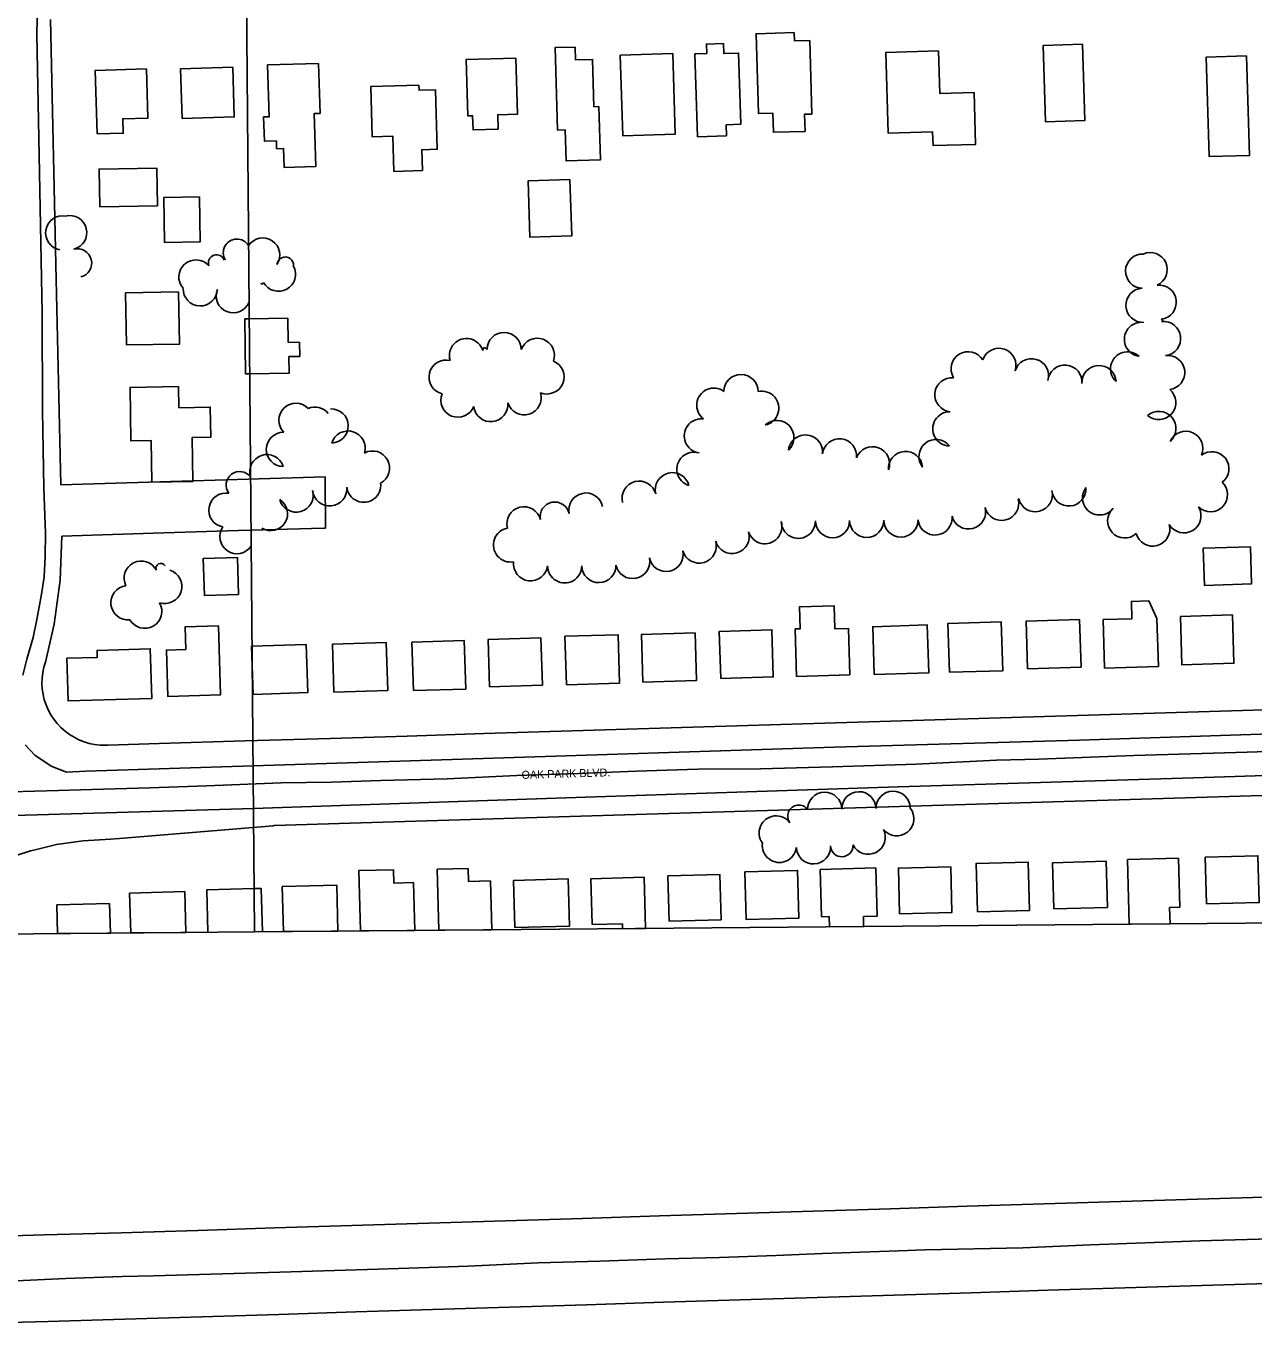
# Model space of a CAD drawing. Extents: x -2233 to 187241, y 4582 to 150524.
# Drawn here: x 114881 to 115599, y 57158 to 57919 of the extents above; entities that cross this region are included whole.
import ezdxf

# ---------------------------------------------------------------- set-up
doc = ezdxf.new("R2010")
doc.units = 0
for name, color, linetype in [('60', 7, 'Continuous'), ('BLDG', 7, 'Continuous'), ('GE_X_CL_2000', 7, 'Continuous'), ('GRID', 7, 'Continuous'), ('ROAD', 7, 'Continuous'), ('ROAD-NAME', 7, 'Continuous'), ('RW_X_Fee_RW', 7, 'Continuous'), ('TREES', 7, 'Continuous')]:
    doc.layers.add(name, color=color, linetype=linetype)

msp = doc.modelspace()

# ---------------------------------------------------------------- linework, layer by layer
at = {"layer": '60'}
for p, q in [((115014.43, 57389.55), (114990.89, 60087.23)), ((114990.89, 60087.23), (115014.43, 57389.55)), ((120014.24, 57433.19), (115014.43, 57389.55)), ((115014.43, 57389.55), (110014.63, 57345.92))]:
    msp.add_line(p, q, dxfattribs=at)
at = {"layer": 'BLDG'}
for p, q in [((115011.31, 57748.02), (115033.94, 57748.41)), ((115524.99, 57431.91), (115554.72, 57432.72)), ((115526.01, 57394.02), (115524.99, 57431.91)), ((115554.72, 57432.72), (115555.5, 57403.96)), ((115075.48, 57425.39), (115095.67, 57425.93)), ((115076.44, 57390.1), (115075.48, 57425.39)), ((115095.67, 57425.93), (115095.89, 57418.06)), ((115121.31, 57426.13), (115139.31, 57426.62)), ((115122.26, 57390.5), (115121.31, 57426.13)), ((115139.31, 57426.62), (115139.51, 57418.99)), ((115377.77, 57426.92), (115345.3, 57426.05)), ((115345.3, 57426.05), (115346.05, 57398.37)), ((115378.54, 57398.69), (115377.77, 57426.92)), ((115062.52, 57416.9), (115030.67, 57416.04)), ((115030.67, 57416.04), (115031.38, 57389.7)), ((115063.25, 57389.98), (115062.52, 57416.9)), ((115095.89, 57418.06), (115107.42, 57418.37)), ((115107.42, 57418.37), (115108.17, 57390.37)), ((115139.51, 57418.99), (115152.51, 57419.34)), ((115152.51, 57419.34), (115153.28, 57390.77)), ((115242.28, 57421.51), (115211.19, 57420.67)), ((115211.19, 57420.67), (115211.92, 57393.8)), ((115243.1, 57391.55), (115242.28, 57421.51)), ((114973.6, 57413.16), (114941.4, 57412.29)), ((114941.4, 57412.29), (114942.03, 57388.92)), ((114974.24, 57389.2), (114973.6, 57413.16)), ((114929.69, 57406.18), (114898.82, 57405.35)), ((114898.82, 57405.35), (114899.28, 57388.55)), ((114930.16, 57388.82), (114929.69, 57406.18)), ((115555.5, 57403.96), (115549.55, 57403.8)), ((115549.55, 57403.8), (115549.81, 57394.23)), ((115211.92, 57393.8), (115229.59, 57394.29)), ((115229.59, 57394.29), (115229.67, 57391.43)), ((115346.05, 57398.37), (115350.46, 57398.49)), ((115350.46, 57398.49), (115350.62, 57392.49)), ((115350.62, 57392.49), (115370.64, 57392.66)), ((115370.48, 57398.47), (115378.54, 57398.69)), ((115370.64, 57392.66), (115370.48, 57398.47)), ((115549.81, 57394.23), (115526.01, 57394.02)), ((114899.28, 57388.55), (114930.16, 57388.82)), ((114942.03, 57388.92), (114974.24, 57389.2)), ((115031.38, 57389.7), (115063.25, 57389.98)), ((115108.17, 57390.37), (115076.44, 57390.1)), ((115153.28, 57390.77), (115122.26, 57390.5)), ((115229.67, 57391.43), (115243.1, 57391.55))]:
    msp.add_line(p, q, dxfattribs=at)
for points in [[(115330.08, 57915.35), (115330.22, 57910.44), (115339.11, 57910.7), (115340.42, 57867.69), (115336.07, 57867.55), (115336.37, 57857.58), (115317.89, 57857.02), (115317.54, 57868.27), (115309.12, 57868.02), (115307.7, 57914.68)], [(115201.94, 57906.89), (115202.17, 57899.37), (115212.06, 57899.67), (115212.9, 57871.95), (115215.72, 57872.03), (115216.67, 57840.91), (115196.66, 57840.31), (115196.11, 57858.41), (115191.71, 57858.27), (115190.23, 57906.52)], [(115258.97, 57903.04), (115260.41, 57855.94), (115229.78, 57855.01), (115228.34, 57902.11)], [(115290.5, 57854.94), (115290.3, 57861.48), (115298.8, 57861.73), (115297.53, 57903.35), (115288.8, 57903.08), (115288.63, 57908.86), (115278.72, 57908.57), (115278.88, 57903.15), (115272.01, 57902.94), (115273.49, 57854.42)], [(115414.45, 57904.66), (115415.21, 57879.64), (115435.21, 57880.24), (115436.13, 57849.99), (115411.23, 57849.23), (115410.98, 57857.25), (115385.06, 57856.45), (115383.62, 57903.72)], [(115498.54, 57908.48), (115499.9, 57863.87), (115476.94, 57863.17), (115475.58, 57907.78)], [(114972.04, 57865.06), (115002.62, 57866), (115001.73, 57895.07), (114971.15, 57894.13)], [(115051.92, 57897.3), (115052.81, 57868.11), (115049.32, 57868), (115050.27, 57836.98), (115031.82, 57836.41), (115031.47, 57847.52), (115027.36, 57847.4), (115027.22, 57851.99), (115020.18, 57851.78), (115019.75, 57866), (115023.02, 57866.1), (115022.09, 57896.39)], [(115167.24, 57900.43), (115168.25, 57867.69), (115156.66, 57867.34), (115156.91, 57858.91), (115142.24, 57858.46), (115141.99, 57866.74), (115139.2, 57866.66), (115138.19, 57899.55)], [(115594.52, 57901.73), (115596.3, 57843.52), (115572.79, 57842.8), (115571.02, 57901.01)], [(114922.42, 57856.04), (114937.65, 57856.51), (114937.39, 57864.93), (114952.11, 57865.37), (114951.24, 57894.12), (114921.3, 57893.22)], [(115110.58, 57884.6), (115110.66, 57881.59), (115120.25, 57881.88), (115121.32, 57847.13), (115112.27, 57846.85), (115112.64, 57834.63), (115095.96, 57834.13), (115095.33, 57854.74), (115083.32, 57854.37), (115082.41, 57883.74)], [(114923.93, 57813.53), (114957.7, 57814.13), (114957.31, 57836.11), (114923.54, 57835.5)], [(115198.92, 57829.37), (115199.93, 57796.42), (115175.47, 57795.67), (115174.46, 57828.62)], [(114982.24, 57819.24), (114982.71, 57793.03), (114961.8, 57792.66), (114961.34, 57818.86)], [(114970.04, 57763.71), (114970.58, 57733.24), (114939.59, 57732.69), (114939.04, 57763.16)], [(114970.02, 57708.36), (114970.24, 57696.01), (114988.51, 57696.34), (114988.81, 57678.78), (114977.97, 57678.58), (114978.43, 57652.89), (114954.45, 57652.46), (114954.02, 57676.82), (114942.19, 57676.62), (114941.63, 57707.86)], [(115569.9, 57592.15), (115597.44, 57593), (115596.78, 57614.69), (115569.24, 57613.85)], [(115004.47, 57608.5), (115005.13, 57586.89), (114985.11, 57586.27), (114984.45, 57607.89)], [(115510.67, 57572.14), (115527.54, 57572.65), (115527.23, 57582.79), (115537.5, 57583.1), (115542.18, 57572.75), (115543.04, 57544.67), (115511.54, 57543.71)], [(115330.56, 57566.74), (115333.62, 57566.83), (115333.23, 57579.63), (115353.34, 57580.24), (115353.75, 57566.75), (115361.7, 57566.99), (115362.53, 57539.89), (115331.41, 57538.95)], [(115555.9, 57573.91), (115586.27, 57574.84), (115587.14, 57546.57), (115556.76, 57545.65)], [(114974.26, 57554.69), (114973.87, 57567.83), (114993.28, 57568.42), (114994.52, 57528.07), (114963.76, 57527.13), (114962.93, 57554.35)], [(115376.88, 57540.04), (115408.74, 57541.01), (115407.88, 57568.98), (115376.02, 57568)], [(115420.82, 57541.31), (115451.97, 57542.26), (115451.1, 57570.82), (115419.95, 57569.87)], [(115466.5, 57543.4), (115497.79, 57544.35), (115496.94, 57572.14), (115465.66, 57571.18)], [(115107.35, 57530.6), (115137.95, 57531.53), (115137.08, 57559.82), (115106.48, 57558.88)], [(115151.94, 57532.85), (115182.78, 57533.78), (115181.94, 57561.44), (115151.1, 57560.5)], [(115196.85, 57534.09), (115227.9, 57535.04), (115227.04, 57563.31), (115195.98, 57562.36)], [(115241.57, 57535.54), (115272.9, 57536.5), (115272.05, 57564.34), (115240.72, 57563.39)], [(115287.05, 57537.68), (115317.81, 57538.62), (115316.97, 57566.19), (115286.21, 57565.25)], [(114904.62, 57549.53), (114922.47, 57550.07), (114922.35, 57554.1), (114953.51, 57555.05), (114954.39, 57526.09), (114905.38, 57524.6)], [(115013.59, 57528.44), (115045.56, 57529.42), (115044.69, 57557.5), (115012.74, 57556.53)], [(115060.84, 57529.65), (115092.34, 57530.61), (115091.48, 57558.65), (115059.99, 57557.69)], [(115437.18, 57401.29), (115467.57, 57402.1), (115466.81, 57430.37), (115436.42, 57429.55)], [(115481.86, 57402.99), (115513.22, 57403.83), (115512.49, 57430.82), (115481.13, 57429.97)], [(115571.11, 57405.87), (115601.95, 57406.7), (115601.22, 57434.05), (115570.38, 57433.22)], [(115256.91, 57395.83), (115287.26, 57396.64), (115286.55, 57423.07), (115256.2, 57422.25)], [(115301.17, 57424.66), (115332.04, 57425.49), (115332.8, 57397.64), (115301.92, 57396.81)], [(115391.67, 57400.14), (115422.3, 57400.96), (115421.59, 57427.63), (115390.94, 57426.82)], [(115166.64, 57392.13), (115198.64, 57392.99), (115197.9, 57420.52), (115165.9, 57419.66)]]:
    msp.add_lwpolyline(points, close=True, dxfattribs=at)
for points in [[(115011.59, 57715.81), (115009.25, 57715.77), (115008.68, 57747.96), (115011.31, 57748.02)], [(115033.94, 57748.41), (115034.2, 57734.15), (115040.72, 57734.26), (115040.86, 57726), (115034.59, 57725.89), (115034.77, 57716.22), (115011.59, 57715.81)], [(115012.98, 57556.53), (115012.74, 57556.53), (115013.07, 57545.53)], [(115014.21, 57414.85), (114986.46, 57414.11), (114987.13, 57389.32)], [(115019.01, 57389.59), (115018.32, 57414.96), (115014.21, 57414.85)]]:
    msp.add_lwpolyline(points, dxfattribs=at)
at = {"layer": 'GE_X_CL_2000'}
for points in [[(114844.17, 57470.72), (114899.9, 57472.29), (114912.73, 57472.55), (114953.21, 57473.76), (114986.42, 57475.03), (115030.1, 57476.62), (115059.54, 57477.06), (115088.32, 57477.98), (115127.09, 57479.11), (115167.82, 57480.89), (115203.99, 57482.2), (115237.88, 57483.56), (115273.59, 57484.65), (115310.42, 57484.92), (115352.49, 57486.1), (115401.28, 57487.56), (115448.38, 57489.87), (115473.17, 57490.54), (115528.63, 57492.67), (115594.96, 57494.66), (115658.5, 57496.72)], [(114858.27, 57184.68), (114904.11, 57186.92), (114937.03, 57188.09), (114955.27, 57188.5), (115029.17, 57190.61), (115086.75, 57192.41), (115110.59, 57193.19), (115139.46, 57194.2), (115180.24, 57196.08), (115216.42, 57197.02), (115254.52, 57198.35), (115286.35, 57199.19), (115319.37, 57200.28), (115346.62, 57201.54), (115391.12, 57203.12), (115406.61, 57203.69), (115463.73, 57204.93), (115503.24, 57206.59), (115567.34, 57208.97), (115643.21, 57210.98)]]:
    msp.add_lwpolyline(points, dxfattribs=at)
at = {"layer": 'GRID'}
msp.add_line((114990.89, 60087.23), (115014.43, 57389.55), dxfattribs=at)
msp.add_line((114990.89, 60087.23), (115014.43, 57389.55), dxfattribs=at)
at = {"layer": 'ROAD'}
msp.add_line((115013.81, 57461.73), (115030.67, 57462.22), dxfattribs=at)
for points in [[(114878.95, 57539.73), (114881.34, 57548.93), (114884.93, 57561.7), (114887.32, 57573.15), (114889.85, 57587.03), (114891.36, 57597.23), (114891.94, 57609.06), (114892.28, 57622.76), (114891.32, 57649.06), (114890.5, 57694.3), (114890.2, 57751.26), (114888.23, 57853.77), (114887.18, 57913.98), (114887.33, 57923.61), (114890.34, 57929.18), (114896.04, 57933.49), (114902.55, 57935.42), (114916.63, 57935.47), (115009.65, 57938.08)], [(115967.66, 57397.87), (115967.22, 57439.54), (115967.02, 57653.57), (115942.42, 57654.18), (115942.42, 57570.13), (115943.09, 57551.47), (115943.01, 57542.96), (115940.75, 57535.02), (115936.99, 57528.64), (115931.48, 57524.14), (115925.27, 57520.39), (115917.82, 57517.03), (115907.8, 57515.66), (115875.7, 57514.71), (115738.38, 57509.58), (115496.79, 57501.73), (115353.35, 57497.56), (115136.04, 57490.56), (115013.59, 57486.62)], [(115013.59, 57486.62), (114915.79, 57483.48), (114904.41, 57482.99), (114895.58, 57486.46), (114886.02, 57492.85), (114880.4, 57498.92)], [(115030.67, 57462.22), (115208.05, 57468.23), (115390.86, 57474.29), (115563.6, 57479.61), (115858.58, 57489.26), (115890.12, 57490.47), (115911.08, 57491.13), (115918.59, 57490.92), (115925.1, 57488.73), (115930.47, 57485.34), (115935.23, 57480.33), (115938.73, 57475.82), (115942.03, 57469.74), (115943.09, 57465.3), (115943.56, 57448.77), (115943.85, 57397.67)], [(114786.02, 57387.56), (114797.2, 57403.6), (114820.03, 57436.87), (114826.3, 57443.87), (114833.51, 57449.49), (114840.9, 57453.18), (114850.8, 57456.35), (114858.87, 57457.28), (114887.4, 57457.98), (115013.81, 57461.73)]]:
    msp.add_lwpolyline(points, dxfattribs=at)
at = {"layer": 'RW_X_Fee_RW'}
for p, q in [((114901.15, 57650.97), (115055.81, 57655.69)), ((115055.81, 57655.69), (115055.94, 57625.68)), ((114927.3, 57498.7), (114928.83, 57498.74))]:
    msp.add_line(p, q, dxfattribs=at)
for points in [[(114895.1, 57922.96), (114898.49, 57770.94), (114899.82, 57710.95), (114901.15, 57650.97)], [(114892.19, 57547.32), (114897.36, 57569.5), (114900.88, 57595.13), (114901.82, 57620.98)], [(114901.82, 57620.98), (114955.1, 57622.6), (115005.08, 57624.13), (115055.06, 57625.65), (115055.94, 57625.68)], [(114892.19, 57547.32), (114891.3, 57544.35), (114890.61, 57541.13), (114890.24, 57537.96), (114890.14, 57534.77), (114890.32, 57531.57), (114890.78, 57528.41), (114891.52, 57525.3), (114892.52, 57522.27), (114893.79, 57519.33), (114895.3, 57516.52), (114897.06, 57513.85), (114899.04, 57511.34), (114901.24, 57509.01), (114903.62, 57506.89), (114906.19, 57504.98), (114908.91, 57503.31), (114911.77, 57501.88), (114914.74, 57500.7), (114917.8, 57499.78), (114920.93, 57499.14), (114924.11, 57498.78), (114927.3, 57498.7)], [(114928.83, 57498.74), (114958.75, 57499.66), (115008.83, 57501.18), (115058.8, 57502.71), (115103.78, 57504.08), (115148.76, 57505.45), (115193.75, 57506.82), (115238.73, 57508.19), (115283.71, 57509.56), (115328.69, 57510.93), (115373.67, 57512.3), (115418.65, 57513.67), (115463.63, 57515.04), (115508.61, 57516.41), (115553.59, 57517.78), (115598.57, 57519.15), (115643.55, 57520.52), (115688.53, 57521.89), (115733.51, 57523.26), (115778.49, 57524.64), (115823.47, 57526.01), (115868.45, 57527.38), (115908.44, 57528.6)], [(115025.9, 57451.68), (115070.32, 57453.03), (115115.3, 57454.4), (115160.28, 57455.77), (115205.26, 57457.14), (115250.24, 57458.51), (115295.22, 57459.89), (115340.2, 57461.26), (115385.18, 57462.63), (115430.16, 57464), (115475.14, 57465.37), (115520.12, 57466.74), (115565.1, 57468.11), (115610.08, 57469.48), (115655.06, 57470.85), (115700.04, 57472.22), (115745.02, 57473.59), (115790, 57474.96), (115834.98, 57476.33), (115879.96, 57477.7), (115909.94, 57478.62)], [(115025.9, 57451.68), (115025.34, 57451.63), (114980.43, 57447.91), (114935.52, 57444.19), (114930.18, 57443.77)], [(114930.18, 57443.77), (114914.23, 57442.83), (114898.69, 57440.56), (114890, 57438.51), (114886.1, 57437.59), (114883.41, 57436.96), (114868.49, 57432.05), (114854.04, 57425.89), (114840.18, 57418.5), (114835.89, 57415.71), (114827.01, 57409.95), (114814.62, 57400.3), (114803.11, 57389.62), (114792.56, 57377.99), (114783.04, 57365.49)], [(114936.53, 57213.65), (114981.37, 57215.05), (115026.35, 57216.46), (115071.33, 57217.86), (115116.31, 57219.27), (115161.29, 57220.68), (115206.27, 57222.08), (115251.24, 57223.49), (115296.22, 57224.9), (115341.2, 57226.3), (115386.18, 57227.71), (115431.16, 57229.12), (115476.14, 57230.52), (115521.12, 57231.93), (115566.1, 57233.33), (115611.08, 57234.74), (115656.06, 57236.15), (115701.04, 57237.55), (115746.02, 57238.96), (115791, 57240.37), (115835.98, 57241.77), (115880.95, 57243.18), (115913.63, 57244.2)], [(114756.77, 57208.52), (114801.58, 57209.8), (114846.56, 57211.08), (114891.54, 57212.36), (114936.53, 57213.65)], [(114938.69, 57163.13), (114983.67, 57164.54), (115028.65, 57165.95), (115073.62, 57167.35), (115118.6, 57168.76), (115163.58, 57170.17), (115208.56, 57171.57), (115253.54, 57172.98), (115298.52, 57174.38), (115343.5, 57175.79), (115388.48, 57177.2), (115433.46, 57178.6), (115478.44, 57180.01), (115523.42, 57181.42), (115568.39, 57182.82), (115613.37, 57184.23), (115658.35, 57185.64), (115703.33, 57187.04), (115748.31, 57188.45), (115793.29, 57189.86), (115838.27, 57191.26), (115883.25, 57192.67), (115915.93, 57193.69)], [(114758.52, 57157.99), (114803.74, 57159.28), (114848.72, 57160.57), (114893.7, 57161.85), (114938.69, 57163.13)]]:
    msp.add_lwpolyline(points, dxfattribs=at)
at = {"layer": 'TREES'}
for centre, radius, start, end in [((114902.24, 57798.22), 10, 80.49339, 260.49339), ((114906.36, 57798.39), 10, 284.30301, 104.30301), ((114910.89, 57780.61), 8.34, 284.30301, 104.30301), ((115004.16, 57786.62), 7.98, 31.99681, 211.99681), ((115019.24, 57785.29), 10, 326.19616, 146.19616), ((114980.19, 57772.44), 10, 41.49891, 221.49891), ((114992.23, 57780.62), 4.81, 18.93578, 198.93578), ((115032.4, 57779.29), 4.86, 354.94043, 174.94043), ((115533.79, 57775.87), 10, 88.29888, 268.29888), ((115538.18, 57776.74), 10, 294.10875, 114.10875), ((115028.47, 57774.06), 10, 208.69727, 28.69727), ((114982.69, 57765.51), 10, 178.28971, 358.28971), ((115001.96, 57761.45), 10, 157.91614, 337.91614), ((115018.87, 57769.09), 0.848, 191.81885, 11.81885), ((115534.01, 57755.89), 10, 92.92584, 272.92584), ((115543.48, 57757.69), 10, 277.01952, 97.01952), ((115533.11, 57736), 10, 81.91769, 261.91769), ((115544.79, 57747.08), 0.69, 276.88183, 96.88183), ((115546.07, 57736.46), 10, 276.88184, 96.88184), ((115138.39, 57726.5), 10, 16.81164, 196.81164), ((115160.4, 57730.05), 10, 359.6949, 179.6949), ((115179.82, 57726.64), 10, 340.39591, 160.39591), ((115149.18, 57729.75), 1.27, 16.2343, 196.2343), ((115431.76, 57718.78), 10, 31.50473, 211.50473), ((115449.74, 57720.77), 10, 341.12855, 161.12855), ((115524.99, 57718.7), 10, 47.78225, 227.78225), ((115126.48, 57713.89), 10, 76.44086, 256.44086), ((115185.47, 57714.03), 10, 247.8178, 67.8178), ((115468.79, 57714.7), 10, 343.48063, 163.48063), ((115488.34, 57710.97), 10, 354.93017, 174.93017), ((115508.29, 57710.69), 10, 3.45153, 183.45153), ((115548.46, 57716.61), 10, 276.88184, 96.88184), ((115298.96, 57705.49), 10, 359.89828, 179.89828), ((115422.26, 57703.61), 10, 84.40301, 264.40301), ((115172.13, 57701.85), 10, 196.93945, 16.93945), ((115283.01, 57697.47), 10, 53.48973, 233.48973), ((115311.04, 57695.69), 10, 281.97737, 101.97738), ((115543.2, 57699.05), 10, 229.70491, 49.70491), ((115038.65, 57688.65), 10, 44.36398, 224.36398), ((115133.41, 57700.43), 10, 158.08094, 338.08094), ((115152.62, 57697.82), 10, 186.4273, 6.4273), ((115049.71, 57686.44), 10, 38.84961, 113.04507), ((115059.25, 57685.34), 10, 271.76289, 91.76289), ((115275.73, 57679.53), 10, 82.32623, 262.32623), ((115421.04, 57683.66), 10, 88.64998, 268.64998), ((115543.29, 57683.88), 10, 311.0451, 131.0451), ((115031.34, 57671.66), 10, 89.07445, 269.07445), ((115069.13, 57672.44), 10, 343.10942, 163.10942), ((115319.9, 57678.57), 10, 312.78735, 132.78735), ((115559, 57672.28), 10, 336.05283, 156.05283), ((115336.63, 57670.11), 10, 353.53038, 173.53038), ((115356.51, 57667.86), 10, 353.57315, 173.57315), ((115412.96, 57667.46), 10, 38.29103, 218.29103), ((115021.65, 57658.62), 10, 17.72792, 197.72792), ((115083.45, 57660.74), 10, 298.39895, 118.39895), ((115271.43, 57660.06), 10, 72.76729, 252.76729), ((115375.81, 57663.23), 10, 339.44616, 159.44616), ((115395.14, 57660.49), 10, 4.43311, 184.43311), ((115574.25, 57660.31), 10, 307.68614, 127.68614), ((115005.79, 57650.76), 7.92, 37.05738, 217.05738), ((115078.28, 57650.71), 10, 187.08004, 7.08004), ((115239.39, 57643.14), 10, 14.22951, 194.22951), ((115258.77, 57648.05), 10, 14.22951, 194.22951), ((115573.44, 57645.18), 10, 226.16871, 46.16871), ((114997.7, 57636.15), 10, 79.81816, 259.81816), ((115038.81, 57644.95), 10, 195.56467, 15.56467), ((115058.4, 57648.56), 10, 185.29017, 5.29017), ((115208.21, 57636.16), 10, 11.88266, 191.88266), ((115471.05, 57645.2), 10, 194.40093, 14.40093), ((115490.7, 57648.52), 10, 184.76884, 4.76884), ((115508.62, 57643.29), 10, 142.66955, 322.66955), ((115023.93, 57633.96), 9.83, 237.7054, 57.7054), ((115172.01, 57628.1), 10, 14.36602, 194.36602), ((115190.06, 57632.34), 8.54, 11.88266, 191.88266), ((115432.01, 57635.1), 10, 194.54967, 14.54967), ((115451.36, 57640.12), 10, 194.54967, 14.54967), ((115461.2, 57642.68), 0.166, 194.54963, 14.54963), ((115523.31, 57629.84), 10, 132.40709, 312.40709), ((115557.94, 57632.83), 10, 210.94921, 30.94921), ((115312.88, 57626.46), 10, 197.05425, 17.05425), ((115332.44, 57629.63), 10, 181.33166, 1.33166), ((115352.44, 57629.96), 10, 180.60123, 0.60123), ((115372.44, 57630.17), 10, 180.60123, 0.60123), ((115392.44, 57630.39), 10, 180.66792, 0.66792), ((115412.38, 57631.55), 10, 185.95158, 5.95158), ((115004.2, 57620.68), 10, 145.75941, 325.75941), ((115164.13, 57615.78), 10, 100.41779, 280.41779), ((115293.72, 57620.74), 10, 196.21314, 16.21314), ((115539.71, 57625.07), 10, 195.14676, 15.14676), ((115274.52, 57615.15), 10, 196.21224, 16.21224), ((114948.18, 57596.41), 10, 26.95423, 206.95423), ((115175.87, 57604.77), 10, 173.24511, 353.24511), ((115235.58, 57606.09), 10, 192.06575, 12.06575), ((115255.13, 57610.27), 10, 192.06809, 12.06809), ((114959.6, 57602.22), 2.81, 26.95423, 206.95423), ((114961.94, 57591.54), 10, 252.38554, 72.38554), ((115195.8, 57603.56), 10, 179.77906, 359.77906), ((115215.8, 57603.76), 10, 181.36764, 1.36764), ((114940.43, 57581.95), 10, 96.67899, 276.67899), ((114950.25, 57577.01), 10, 209.98048, 29.98048), ((115347.89, 57461.24), 10, 0.82537, 180.82537), ((115367.89, 57461.53), 10, 0.82537, 180.82537), ((115387.89, 57461.82), 10, 0.82537, 180.82537), ((115332.7, 57457.23), 6.47, 36.68331, 216.68331), ((115390.07, 57455.72), 10, 218.57851, 38.57851), ((115319.49, 57447.39), 10, 36.68331, 216.68331), ((115373.34, 57444.95), 10, 207.02201, 27.02201), ((115321.39, 57440.13), 10, 172.60949, 352.60949), ((115341.3, 57439.31), 10, 182.69447, 2.69447), ((115357.86, 57440.09), 6.58, 182.69447, 2.69447)]:
    msp.add_arc(centre, radius, start, end, dxfattribs=at)

# ---------------------------------------------------------------- texts
at = {"layer": 'ROAD-NAME'}
msp.add_text('OAK PARK BLVD.', height=4.68, rotation=1.71922, dxfattribs=at).set_placement((115170.71, 57478.98))

doc.saveas('drawing.dxf')
